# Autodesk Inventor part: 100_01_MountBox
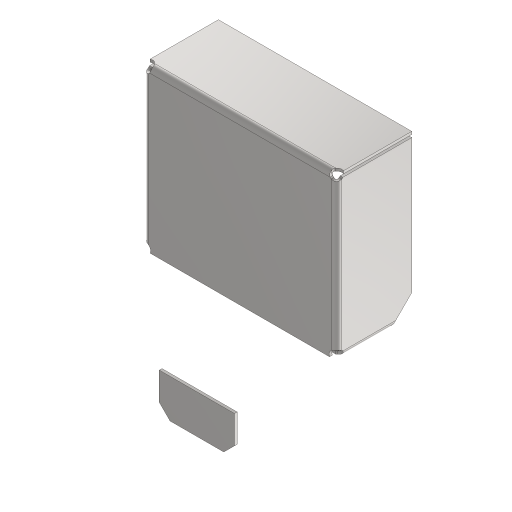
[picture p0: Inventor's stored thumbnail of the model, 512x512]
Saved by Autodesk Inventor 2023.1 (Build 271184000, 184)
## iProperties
Company: Fabian Stasiak CAD Consulting
Category: Autodesk® Inventor® Tutorial Series
Created: 2005-11
Part Number: 100_01_MountBox
Material: Steel
Document SubType Name: Sheet Metal
Designer: F.Stasiak
Density: 1 g/cm^3
Sheet Metal Rule: Steel 2.5 mm/Round
Appearance: Stainless - Brushed
Description: Mounting Box RX7
Catalog Web Link: www.expertbooks.eu
FLATAREA: =<FLAT PATTERN AREA>
Thickness: 2,500 mm
Author: F.Stasiak
Subject: Sheet Metal Design. Basic and Advanced techniques
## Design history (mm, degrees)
node "Powierzchnia1"
  sketch "Szkic2"
    geometry: L1 (-75, 90)-(75, 90); L2 (75, 90)-(75, -90); L3 (75, -90)-(-75, -90); L4 (-75, -90)-(-75, 90); L5 (0, 90)-(0, -90); 2 further points
    constraints: 10 end point, 3 midpoint, 2 parallel, 1 coincident, 1 horizontal, 1 perpendicular
    dimensions: "d2" = 150 distance of L2.end L3.end; "d3" = 180 distance of L1.end L2.end
node "Kołnierz6"
feature "Fazowanie narożnika3" dims "d68" = 20, "d69" = 6, angle "d70" = 45 deg
node "Kołnierz7"
node "Płaszczyzna konstrukcyjna2"
node "Powierzchnia3"
  sketch "Szkic11"
    geometry: L1 (-231, 119.076)-(-195, 119.076); L2 (-195, 119.076)-(-195, 49.076); L3 (-195, 49.076)-(-231, 49.076); L4 (-231, 49.076)-(-231, 119.076); L5 (-142.5, 44.076)-(-145, 44.076) reference; L6 (-142.5, 124.076)-(-145, 124.076) reference; L7 (-145, 169.076)-(-145, -0.924) reference; 1 further point
    constraints: 8 end point, 2 parallel, 1 horizontal, 1 perpendicular
    dimensions: "d82" = 5 distance between parallel lines of L5 L3; "d83" = 5 distance between parallel lines of L6 L1 (= d82); "d84" = 36 distance of L1.start L1.end; "d85" = 50 distance between parallel lines of L7 L2
feature "Fazowanie narożnika4" dims "d91" = 10, "d92" = 6, angle "d93" = 45 deg
feature "Narożnik3" dims "d94" = 10 (= CornerReliefSize), "d95" = 2.5 (= BendRadius), "d96" = 2.5 (= GapSize), "d97" = 0, "d98" = 10, "d104" = 2.5 (= Thickness)
feature "Narożnik4" dims "d99" = 10 (= CornerReliefSize), "d100" = 2.5 (= BendRadius), "d101" = 2.5 (= GapSize), "d102" = 0, "d103" = 10, "d104" = 2.5 (= Thickness)
node "Bryła1"
node "Korpusy bryłowe"
node "Korpusy powierzchniowe"
feature "Płyta1" dims "d104" = 2.5 (= Thickness)
sketch "Szkic9"
  geometry: L1 (0, 70)-(-150, 70); L2 (-150, 70)-(-150, 0); 1 other entity
  constraints: 4 end point, 4 other
feature "Płyta8" dims "d56" = 2.5 (= BendReliefWidth), "d57" = 1.25 (= BendReliefDepth), "d58" = 5 (= MinimumRemnant), "d59" = 2.5 (= BendRadius), "d60" = 70 (= WW), "d61" = 90 deg, "d62" = 2.5 (= BendRadius), "d63" = 10 (= CornerReliefSize), "d64" = 2.5 (= GapSize), "d65" = 2.5 (= JacobiRadiusSize), "d66" = 10, "d67" = 10, "d104" = 2.5 (= Thickness), "SeamGap" = 0.01
feature "Gięcie7" dims "d56" = 2.5 (= BendReliefWidth), "d57" = 1.25 (= BendReliefDepth), "d58" = 5 (= MinimumRemnant), "d59" = 2.5 (= BendRadius), "d60" = 70 (= WW), "d61" = 90 deg, "d62" = 2.5 (= BendRadius), "d104" = 2.5 (= Thickness), "SeamGap" = 0.01
feature "Narożnik1" dims "d60" = 70 (= WW), "d61" = 90 deg, "d63" = 10 (= CornerReliefSize), "d64" = 2.5 (= GapSize), "d65" = 2.5 (= JacobiRadiusSize)
sketch "Szkic10"
  geometry: L1 (50, 0)-(50, 45); L2 (50, 45)-(0, 45); 1 other entity
  constraints: 4 end point, 4 other
feature "Płyta9" dims "d71" = 2.5 (= BendReliefWidth), "d72" = 1.25 (= BendReliefDepth), "d73" = 5 (= MinimumRemnant), "d74" = 2.5 (= BendRadius), "d75" = 50, "d76" = 90 deg, "d77" = 2.5 (= BendRadius), "d78" = 10 (= CornerReliefSize), "d79" = 2.5 (= GapSize), "d80" = 2.5 (= JacobiRadiusSize), "d104" = 2.5 (= Thickness), "SeamGap" = 0.01
feature "Gięcie8" dims "d71" = 2.5 (= BendReliefWidth), "d72" = 1.25 (= BendReliefDepth), "d73" = 5 (= MinimumRemnant), "d74" = 2.5 (= BendRadius), "d75" = 50, "d76" = 90 deg, "d77" = 2.5 (= BendRadius), "d104" = 2.5 (= Thickness), "SeamGap" = 0.01
feature "Narożnik2" dims "d75" = 50, "d76" = 90 deg, "d78" = 10 (= CornerReliefSize), "d79" = 2.5 (= GapSize), "d80" = 2.5 (= JacobiRadiusSize)
feature "Płyta10" dims "d86" = 2.5 (= BendRadius), "d87" = 2.5 (= BendReliefWidth), "d89" = 5 (= MinimumRemnant), "d104" = 2.5 (= Thickness)
feature "Gięcie9" dims "d86" = 2.5 (= BendRadius), "d87" = 2.5 (= BendReliefWidth), "d88" = 1.25 (= BendReliefDepth), "d89" = 5 (= MinimumRemnant), "d90" = 2.5 (= BendRadius), "d104" = 2.5 (= Thickness), "SeamGap" = 0.01
other parameters: "Thickness" = 2.5 (derived), "BendRadius" = 2.5 (= Thickness), "BendReliefWidth" = 2.5 (= Thickness), "BendReliefDepth" = 1.25 (= 0.5 x Thickness), "MinimumRemnant" = 5 (= 2 x Thickness), "TransitionRadius" = 2.5 (= BendRadius), "d4" = 2.5 (= BendRadius), "JacobiRadiusSize" = 2.5 (= BendRadius), "GapSize" = 2.5 (= Thickness)
